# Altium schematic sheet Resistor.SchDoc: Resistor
size A; DocumentNumber: 1; SheetNumber: 1; SheetTotal: 1
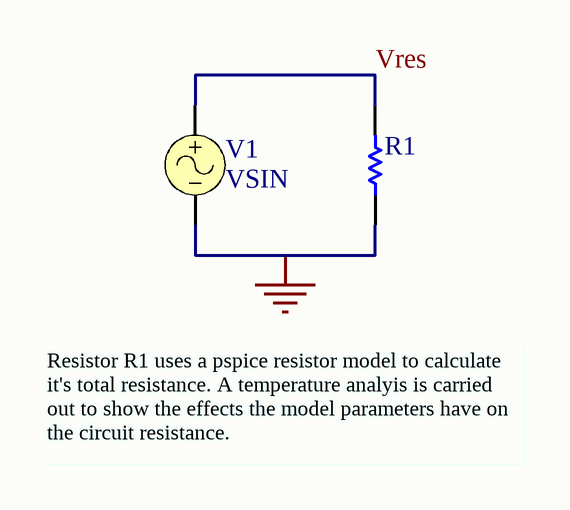
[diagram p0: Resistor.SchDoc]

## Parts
R1  Res1  [AXIAL-0.3]  (value not drawn)
V1  VSIN

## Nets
GND: R1.1 V1.2
Vres: R1.2 V1.1

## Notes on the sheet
- Resistor R1 uses a pspice resistor model to calculate it's total resistance. A temperature analyis is carried out to show the effects the model parameters have on the circuit resistance.

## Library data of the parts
R1 = Res1: Resistor
V1 = VSIN: Sinusoidal Voltage Source; Note: PCB Footprint - Not required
